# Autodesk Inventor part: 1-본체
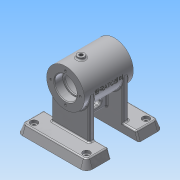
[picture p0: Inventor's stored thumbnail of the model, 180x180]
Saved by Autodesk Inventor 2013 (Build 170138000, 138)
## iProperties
Created: 2016-07
Part Number: 1-본체
Material: 알루미늄 6061
Document SubType Name: Modeling
Designer: Administrator
Density: 2.71 g/cm^3
Mass: 498.887 g
Surface Area: 543.459 cm^2
Volume: 184.091 cm^3
Author: Administrator
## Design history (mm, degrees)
sketch "스케치1"
  geometry: C1 r 27 at (0, 70); 1 further point
  constraints: 1 centre point, 1 vertical alignment
  dimensions: "d0" = 54 diameter of C1; "d1" = 70 distance of point (0, 0) C1.centre
extrude "돌출1" new body sketch "스케치1" stored distance "d2" = 70; taper "d3" = 0 deg
node "작업 평면1"
sketch "스케치2"
  geometry: L1 (-50, 0)-(50, 0); L2 (-45.632, 12)-(45.632, 12); L3 (50, 0)-(45.632, 12); L4 (-50, 0)-(-45.632, 12); 2 further points
  constraints: 8 end point, 2 horizontal alignment, 1 horizontal, 1 midpoint, 1 parallel
  dimensions: "d5" = 100 distance of L1.start L1.end; "d7" = 50 distance of point (0, 0) L1.start; "d8" = 12 distance between parallel lines of L1 L2; "d9" = 70 deg angle of L1 L3; "d11" = 70 deg angle of L1 L4
extrude "돌출2" join sketch "스케치2" distance "d12" = 35; taper "d13" = 0 deg
feature "면 기울기2" dims angle "d17" = 20 deg
fillet "모깎기2" dims "d18" = 5, "d19" = 10
fillet "모깎기3" dims "d20" = 10, "d21" = 5
sketch "스케치3"
  geometry: L1 (95.632, -12)-(4.368, -12) reference; L2 (23, -12)-(23, -70); L3 (77, -12)-(77, -70); L4 (8.59, -12)-(91.41, -12) reference; L5 (23, -70)-(77, -70); L6 (77, -12)-(23, -12); A1 r 27 centre (50, -70) between (23, -70) and (77, -70) reference; 1 further point
  constraints: 8 end point, 2 point on circle, 2 point on line, 1 parallel, 1 perpendicular
  dimensions: "d22" = 27 distance from line of point (50, 0) L2; "d23" = 27 distance from line of point (50, 0) L3
extrude "돌출3" join sketch "스케치3" distance "d24" = 8; taper "d25" = 0 deg
sketch "스케치5"
  geometry: L1 (-22, 22)-(-22, 62); L2 (-22, 62)-(22, 62); L3 (22, 62)-(22, 22); L4 (22, 22)-(-22, 22); L5 (-35, 43)-(35, 43) reference; 1 further point
  constraints: 8 end point, 2 parallel, 1 perpendicular, 1 vertical
  dimensions: "d29" = 21 distance between parallel lines of L4 L5; "d30" = 40 distance between parallel lines of L2 L4; "d31" = 22 distance from line of L3 point (0, 0); "d32" = 22 distance from line of point (0, 0) L1
extrude "돌출4" join sketch "스케치5" stored distance "d33" = 8; taper "d34" = 0 deg
sketch "스케치6"
  geometry: L1 (-22, -20)-(-22, 20) reference; L2 (-35.5, 8)-(-35.5, -8); L3 (-28.5, 8)-(-28.5, -8); A1 r 3.5 centre (-32, 8) between (-35.5, 8) and (-28.5, 8); A2 r 3.5 centre (-32, -8) between (-35.5, -8) and (-28.5, -8); 1 further point
  constraints: 4 end point, 4 point on circle, 2 centre point, 2 tangent, 1 parallel, 1 vertical alignment
  dimensions: "d35" = 7 diameter of A1; "d36" = 7 diameter of A2; "d37" = 16 distance of A2.centre A1.centre; "d38" = 32 horizontal distance of A2.centre point (0, 0); "d39" = 8 vertical distance of point (0, 0) A1.centre; "d40" = 16 distance of L3.start L3.end
extrude "돌출5" cut sketch "스케치6" distance "d41" = 20; taper "d42" = 0 deg
node "작업 평면2"
sketch "스케치7"
  geometry: L1 (-27, -35)-(27, -35) reference; C1 r 5 at (0, -13); 1 further point
  constraints: 1 centre point, 1 vertical alignment
  dimensions: "d44" = 10 diameter of C1; "d45" = 22 distance from line of C1.centre L1
extrude "돌출6" join sketch "스케치7" distance "d46" = 20; taper "d47" = 0 deg
sketch "스케치8"
  geometry: L1 (-47.948, 70)-(56.24, 70); L2 (50, 0)-(-50, 0) reference; L3 (0, 70)-(15.898, 44.559); 2 further points
  constraints: 4 end point, 1 horizontal, 1 midpoint, 1 point on line, 1 vertical alignment
  dimensions: "d48" = 70 distance between parallel lines of L2 L1; "d49" = 30 distance of L3.start L3.end; "d50" = 58 deg angle of L1 L3
node "작업 평면3"
sketch "스케치9"
  geometry: C1 r 6 at (0, 0); 2 further points
  constraints: 1 centre point, 1 coincident
  dimensions: "d51" = 12 diameter of C1
extrude "돌출7" join sketch "스케치9" distance "d53" = 20; taper "d54" = 0 deg
sketch "스케치10"
  geometry: C1 r 27 at (0, 0) reference; C2 r 16 at (0, 0); 1 further point
  constraints: 1 centre point, 1 coincident
  dimensions: "d55" = 32 diameter of C2
extrude "돌출8" cut sketch "스케치10" distance "d56" = 12; taper "d57" = 0 deg
sketch "스케치11"
  geometry: C1 r 16 at (0, 0) reference; C2 r 14 at (0, 0); 1 further point
  constraints: 1 centre point, 1 coincident
  dimensions: "d58" = 28 diameter of C2
extrude "돌출9" cut sketch "스케치11" distance "d59" = 2; taper "d60" = 0 deg
sketch "스케치12"
  geometry: C1 r 14 at (0, 0) reference; C2 r 22 at (0, 0); 1 further point
  constraints: 1 centre point, 1 coincident
  dimensions: "d61" = 44 diameter of C2
extrude "돌출10" cut sketch "스케치12" distance "d62" = 42; taper "d63" = 0 deg
sketch "스케치13"
  geometry: L1 (-8.59, 4.078)-(-8.59, 30.632) reference; L2 (82.964, -4.368)-(-0.145, -4.368) reference; L3 (41.41, 118.945)-(41.41, -15.828); 3 further points
  constraints: 2 end point, 1 perpendicular, 1 symmetric about line, 1 vertical alignment
  dimensions: "d64" = 12.5 distance from line of L1 point (3.91, 8.132); "d65" = 12.5 distance from line of point (3.91, 8.132) L2
hole "구멍1" sketch "스케치13" at (3.91, 8.132), (78.91, 8.132) diameter "d66" = 6; stored, may be unused: countersink angle "d70" = 90 deg, drill point angle "d72" = 118 deg; dims "d67" = 6, "d68" = 10, "d69" = 4, "d71" = 8
node "작업 평면4"
sketch "스케치14"
  geometry: L1 (-35, 97)-(-35, 43) reference; 2 further points
  constraints: 1 other
  dimensions: "d74" = 35 distance from line of point (0, 70) L1; "d75" = 70 distance of point (0, 70) point (0, 0)
feature "엠보싱1" sketch "스케치14" dims "d76" = 0.5, "d77" = 0
hole "구멍2" diameter "d80" = 5.188; stored, may be unused: countersink angle "d84" = 90 deg, drill point angle "d86" = 118 deg; dims "d78" = 10, "d79" = 10, "d81" = 30, "d82" = 10, "d83" = 4, "d85" = 30
hole "구멍3" diameter "d89" = 5.188; stored, may be unused: countersink angle "d93" = 90 deg, drill point angle "d95" = 118 deg; dims "d87" = 10, "d88" = 10, "d90" = 30, "d91" = 10, "d92" = 4, "d94" = 30
fillet "모깎기4" dims "d96" = 0.3
fillet "모깎기5" dims "d97" = 2
fillet "모깎기6" dims "d98" = 2
fillet "모깎기7" dims "d99" = 2
fillet "모깎기8" dims "d100" = 2
chamfer "모따기1" distance "d101" = 1; stored, may be unused: second distance "d102" = 2, angle "d103" = 45 deg
fillet "모깎기9" dims "d104" = 2
fillet "모깎기10" dims "d105" = 2
fillet "모깎기11" dims "d106" = 2
fillet "모깎기12" dims "d107" = 2
sketch "스케치16"
  geometry: C1 r 27 at (0, 0) reference; 2 further points
  constraints: 1 vertical alignment
  dimensions: "d108" = 21 distance of C1.centre point (0, 21)
hole "구멍4" sketch "스케치16" at (0, 21) diameter "d109" = 3.242; stored, may be unused: countersink angle "d113" = 90 deg, drill point angle "d115" = 118 deg; dims "d110" = 8, "d111" = 10, "d112" = 4, "d114" = 10
node "솔리드1"
mirror "대칭1"
mirror "대칭2"
mirror "대칭3"
mirror "대칭4"
pattern_circular "원형 패턴1" dims angle "d117" = 360 deg
mirror "대칭5"
other parameters: "d4" = 55, "d73" = 27.5
